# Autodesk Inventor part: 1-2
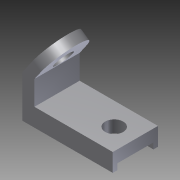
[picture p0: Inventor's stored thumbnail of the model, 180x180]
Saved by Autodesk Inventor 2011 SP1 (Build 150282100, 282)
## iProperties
Created: 2014-01
Part Number: 1-2
Document SubType Name: Modeling
Designer: Administrator
Density: 1 g/cm^3
Author: Administrator
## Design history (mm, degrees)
sketch "草图1"
  geometry: L1 (-15, 7.5)-(-15, -7.5); L2 (-15, -7.5)-(15, -7.5); L3 (15, -7.5)-(15, 7.5); L4 (15, 7.5)-(-15, 7.5); 3 further points
  constraints: 8 end point, 2 midpoint, 2 perpendicular, 1 horizontal alignment, 1 parallel, 1 vertical, 1 vertical alignment
  dimensions: "d0" = 15 distance of L1.start L1.end; "d1" = 30 distance of L1.end L2.end
extrude "拉伸1" new body sketch "草图1" distance "d2" = 6; taper "d3" = 0 deg
sketch "草图3"
  geometry: L1 (-15, -7.5)-(-15, 7.5) reference; L2 (-8.05, -5.84)-(-15, -5.84); L3 (-8.05, 5.84)-(-15, 5.84); L4 (-15, -5.84)-(-15, 5.84); A1 r 5.84 centre (-8.05, 0) between (-8.05, -5.84) and (-8.05, 5.84); 1 further point
  constraints: 6 end point, 2 perpendicular, 2 point on circle, 2 point on line, 2 tangent, 1 centre point, 1 collinear
extrude "拉伸3" join sketch "草图3" distance "d9" = 2; taper "d10" = 0 deg
sketch "草图4"
  geometry: L1 (-15, -7.5)-(-15, 7.5) reference; L2 (-7.98, -6.009)-(-15, -6.009); L3 (-7.98, 6.009)-(-15, 6.009); L4 (-15, -6.009)-(-15, 6.009); A1 r 6.009 centre (-7.98, 0) between (-7.98, -6.009) and (-7.98, 6.009); 1 further point
  constraints: 6 end point, 2 perpendicular, 2 point on circle, 2 point on line, 2 tangent, 1 centre point, 1 collinear
extrude "拉伸4" cut sketch "草图4" distance "d11" = 2; taper "d12" = 0 deg
sketch "草图5"
  geometry: C1 r 3 at (-7.98, 0); A1 r 6.009 centre (-7.98, 0) between (-7.98, -6.009) and (-7.98, 6.009) reference; 1 further point
  constraints: 1 centre point, 1 coincident
  dimensions: "d13" = 6 diameter of C1
extrude "拉伸5" cut sketch "草图5" distance "d14" = 4; taper "d15" = 0 deg
sketch "草图6"
  geometry: L1 (30, 6)-(0, 6) reference; L2 (30, 0)-(30, 6) reference; L3 (0, 6)-(0, 14); L4 (4, 14)-(4, 6); L5 (0, 14)-(3.441, 18.915); L6 (4, 14)-(6.125, 17.036); L7 (3.441, 18.915)-(6.125, 17.036); 1 further point
  constraints: 10 end point, 2 perpendicular, 1 parallel, 1 point on line
  dimensions: "d16" = 8 distance of L1.end L3.end; "d17" = 4 distance of L3.end L4.start; "d18" = 6 distance of L3.end L5.end; "d20" = 145 deg angle of L4 L6; "d21" = 145 deg angle of L3 L5; "d23" = 8 distance of L4.start L4.end
extrude "拉伸6" join sketch "草图6" distance "d24" = 15; taper "d25" = 0 deg
sketch "草图7"
  geometry: L1 (6, 0)-(6, 15) reference; A1 r 7.5 centre (6, 7.5) between (6, 0) and (6, 15); 1 further point
  constraints: 2 point on circle, 2 point on line, 1 centre point, 1 midpoint
  dimensions: "d26" = 15 diameter of A1
extrude "拉伸7" join sketch "草图7" distance "d27" = 3.27222; taper "d28" = 0 deg
hole "Hole1" diameter "d31" = 6; stored, may be unused: countersink angle "d35" = 90 deg, drill point angle "d37" = 0 deg; dims "d29" = 10, "d30" = 10, "d32" = 6, "d33" = 4, "d34" = 2, "d36" = 4
node "实体1"
